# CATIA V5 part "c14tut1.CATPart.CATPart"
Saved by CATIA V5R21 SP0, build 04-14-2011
Part number: Part1
Bounding box of the stored display mesh (mm): x 0 to 46, y -104 to 104, z 0 to 68
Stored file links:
  D:\CATIA V5R21 E-RESOURCES\CATIA-V5R21\catia-v5r21-Tut\c14-catia-v5r21-tut\c14-catia-v5r21-tut01\c14-tut1_Cat_v5r21.CATPart
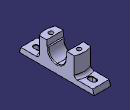
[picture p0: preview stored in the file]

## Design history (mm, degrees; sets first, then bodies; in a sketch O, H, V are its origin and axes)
Body1 (main body)
  Sketch1 on yz-plane, origin (0, 0, 0), H (0, 1, 0), V (0, 0, 1)
    axis line L1 (0, -39.4814) -> (0, 63.0107)
    point P1 (0, -39.4814)
    line L2 (0, 0) -> (104, 0)
    point P3 (104, 0)
    line L3 (104, 0) -> (100, 14)
    point P4 (100, 14)
    line L4 (100, 14) -> (54, 14)
    point P5 (54, 14)
    line L5 (54, 14) -> (54, 68)
    point P6 (54, 68)
    line L6 (54, 68) -> (28, 68)
    point P7 (28, 68)
    line L7 (28, 68) -> (28, 52)
    point P8 (28, 52)
    line L8 (28, 52) -> (23.6643, 52)
    point P9 (23.6643, 52)
    arc A1 centre (0, 48) radius 24 from (23.6643, 52) to (0, 24) cw
    point P10 (0, 48)
    point P11 (0, 24)
    point P12 (-104, 0)
    point P13 (0, 0)
    line L9 (0, 0) -> (-104, 0)
    point P14 (0, 24)
    point P15 (-23.6643, 52)
    point P16 (0, 48)
    arc A2 centre (0, 48) radius 24 from (-23.6643, 52) to (0, 24) ccw
    point P17 (-54, 68)
    point P18 (-28, 68)
    point P19 (-28, 52)
    line L10 (-54, 68) -> (-28, 68)
    line L11 (-28, 68) -> (-28, 52)
    line L12 (-28, 52) -> (-23.6643, 52)
    point P20 (-54, 14)
    line L13 (-54, 14) -> (-54, 68)
    point P21 (-100, 14)
    line L14 (-100, 14) -> (-54, 14)
    line L15 (-104, 0) -> (-100, 14)
    distance P3 P12 = 208
    length L3 V = 14
    distance P3 P6 V = 68
    distance L5 L13 = 108
    distance P18 P7 = 56
    distance P19 P18 = 16
    distance P15 P16 V = 4
    length L15 H = 4
    radius A1 = 24
    coincidence: P1 V, P10 L1, L1 P11, O P13, P11 P14
    vertical: L1 V, L5 V, L7 V
    horizontal: L2 H, L4 H, L6 H, L8 H
    symmetry: P3 P12 L1, O P13 L1, L2 L9 L1, P11 P14 L1, P9 P15 L1, A1 A2 L1, P6 P17 L1, P7 P18 L1, P8 P19 L1, L6 L10 L1, L7 L11 L1, L8 L12 L1, P5 P20 L1, L5 L13 L1, P4 P21 L1, L4 L14 L1, L3 L15 L1
  Pad1: profile Sketch1, direction (1, 0, 0), length 46
  Sketch2 on face of Pad1, origin (0, 0, 14), H (1, 0, 0), V (0, 1, 0)
    arc A1 centre (23, 4) radius 50 from (0, 48.3959) to (46, 48.3959) cw
    point P2 (0, 48.3959)
    point P3 (46, 48.3959)
    reference projected line E1 (46, 54) -> (46, 28) from edge [face of Pad1 | face of Pad1]
    construction line L1 (46, 48.3959) -> (0, 48.3959)
    reference projected line E2 (0, 54) -> (46, 54) from edge [face of Pad1 | face of Pad1]
    axis line L2 (-10.6771, 0) -> (51.171, 0)
    point P4 (-10.6771, 0)
    point P6 (46, -48.3959)
    point P7 (0, -48.3959)
    arc A2 centre (23, -4) radius 50 from (0, -48.3959) to (46, -48.3959) ccw
    line L3 (0, -48.3959) -> (0, 48.3959)
    line L4 (46, 48.3959) -> (46, -48.3959)
    radius A1 = 50
    coincidence: P2 V, P3 E1, P4 H
    horizontal: L1 H, L2 H
    tangency: A1 E2
    symmetry: P3 P6 L2, P2 P7 L2, A1 A2 L2
    vertical: L3 V, L4 V
  Pocket1: profile Sketch2, direction (0, 0, 1), through (limit type 3), outer side
  Sketch3 on face of Pad1, origin (0, 0, 0), H (1, 0, 0), V (0, -1, 0)
    axis line L1 (46, -104) -> (0, 104)
    point P1 (46, -104)
    point P2 (0, 104)
    reference projected point E1 (46, -104) from vertex [face of Pad1 | face of Pad1 | face of Pad1]
    reference projected point E2 (0, 104) from vertex [face of Pad1 | face of Pad1 | face of Pad1]
    point P3 (23, 0)
    line L2 (40.5, 97.5) -> (40.5, -97.5)
    line L3 (40.5, -97.5) -> (5.5, -97.5)
    line L4 (5.5, -97.5) -> (5.5, 97.5)
    line L5 (5.5, 97.5) -> (40.5, 97.5)
    length L3 = 35
    length L2 = 195
    coincidence: P1 E1, P2 E2
    midpoint: P3 L1
    vertical: L2 V, L4 V
    horizontal: L3 H, L5 H
    equidistance: L2 L4 P3, L3 L5 P3
  Pocket2: profile Sketch3, direction (0, 0, 1), length 2
  Sketch4 on face of Pad1, origin (0, 0, 0), H (1, 0, 0), V (0, -1, 0)
    point P1 (23, 39)
    line L1 (36, 52) -> (36, 26)
    line L2 (36, 26) -> (10, 26)
    line L3 (10, 26) -> (10, 52)
    line L4 (10, 52) -> (36, 52)
    construction line L5 (40.5, 0) -> (5.5, 0)
    point P6 (40.5, 0)
    point P7 (5.5, 0)
    reference projected line E1 (40.5, -97.5) -> (40.5, 0) from edge [face of Pad1 | face of Pocket2]
    reference projected line E2 (5.5, 0) -> (5.5, -97.5) from edge [face of Pad1 | face of Pocket2]
    axis line L6 (23, 39) -> (23, 0)
    point P8 (23, 0)
    reference intersected line E3 (0, 104) -> (46, 104) from face of Pad1
    length L3 = 26
    length L4 = 26
    distance L2 E3 = 78
    vertical: L1 V, L3 V, L6 V
    horizontal: L2 H, L4 H, L5 H
    equidistance: L1 L3 P1, L2 L4 P1
    coincidence: P6 H, E1 P6, P7 E2, P8 L5
    midpoint: P8 L5
  Pocket3: profile Sketch4, direction (0, 0, 1), length 10
  Sketch5 on face of Pad1, origin (24.629, 46.0353, 68), H (1, 0, 0), V (0, 1, 0)
    point P1 (-1.629, -85.0353)
    axis line L1 (11.371, -98.0353) -> (-14.629, -72.0353)
    point P2 (11.371, -98.0353)
    point P3 (-14.629, -72.0353)
    reference projected point E1 (11.371, -98.0353) from vertex [face of Pocket3 | face of Pocket3 | face of Pocket3]
    reference projected point E2 (-14.629, -72.0353) from vertex [face of Pocket3 | face of Pocket3 | face of Pocket3]
    coincidence: P2 E1, P3 E2
    midpoint: P1 L1
  Hole1: placed by Sketch5, at (23, -39, 68) direction (0, 0, -1), diameter 12, through (limit type 3)
  Sketch6 on face of Pad1, origin (0, 0, 14), H (1, 0, 0), V (0, 1, 0)
    construction line L1 (23, -71) -> (23, -81)
    point P2 (23, -81)
    line L2 (29, -71) -> (29, -81)
    line L3 (17, -81) -> (17, -71)
    arc A1 centre (23, -81) radius 6 from (29, -81) to (17, -81) cw
    arc A2 centre (23, -71) radius 6 from (17, -71) to (29, -71) cw
    reference projected line E1 (46, -54) -> (46, -100) from edge of Pad1
    reference projected line E2 (0, -104) -> (46, -104) from edge [face of Pad1 | face of Pad1]
    distance L1 E1 = 23
    distance P2 E2 = 23
    radius A1 = 6
    length L1 = 10
    vertical: L1 V
    tangency: A1 L2, A2 L2, A1 L3, A2 L3
    parallelism: L1 L2
  Pocket4: profile Sketch6, direction (0, 0, -1), through (limit type 3)
  Mirror1: of Pocket3, Sketch4, Hole1, Pocket4, Sketch6, about zx-plane
  Fillet1: radius 8, on 2 edges
  Chamfer1: length 1, angle 45, on 2 edges
  Chamfer2: length 2, angle 45, on edge [face of Pad1 | face of Pad1] (x2)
